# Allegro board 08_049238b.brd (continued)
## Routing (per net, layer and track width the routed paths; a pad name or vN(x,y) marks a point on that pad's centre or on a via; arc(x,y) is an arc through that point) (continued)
D2_10_N: length 102.7
  TOP w0.127: X2.23 43.58,56.71 43.46,56.83 25.06,56.83 13.46,45.23 13.46,36.6 13.14,36.28 12.91,36.28 v2(12.61,35.98)
  L8_SIGNAL w0.127: v2(12.61,35.98) 12.31,36.28 11.87,36.28 11.3,36.85 11.3,44.83 18.03,51.56 18.03,75.84 12.72,81.15 7.78,81.15 7.38,80.76 7.38,80.63 P1.D8
D2_10_P: length 103.1
  TOP w0.127: X2.22 43.58,57.21 43.46,57.09 24.96,57.09 13.21,45.34 13.21,36.71 13.04,36.54 12.91,36.54 v2(12.61,36.84)
  L8_SIGNAL w0.127: P1.C8 7.13,80.63 7.13,80.86 7.67,81.41 12.83,81.41 18.29,75.95 18.29,51.46 11.56,44.73 11.56,36.96 11.98,36.54 12.31,36.54 v2(12.61,36.84)
D2_11_N: length 102.7
  TOP w0.127: X2.21 43.58,57.71 43.46,57.83 24.56,57.83 10.92,44.2 10.92,36.55 10.93,36.55 10.93,36.05 10.65,35.78 10.42,35.78 v2(10.12,35.48)
  L8_SIGNAL w0.127: P1.D7 7.38,78.13 7.38,78.26 7.61,78.49 12.47,78.49 16.76,74.19 16.76,52.2 9.02,44.45 9.02,36.47 9.61,35.88 9.72,35.88 v2(10.12,35.48)
D2_11_P: length 103.1
  TOP w0.127: v2(10.12,36.33) 10.42,36.03 10.55,36.03 10.68,36.16 10.68,36.44 10.67,36.45 10.67,44.3 24.46,58.09 43.46,58.09 43.58,58.21 X2.20
  L8_SIGNAL w0.127: P1.C7 7.13,78.13 7.13,78.36 7.5,78.74 12.57,78.74 17.02,74.3 17.02,52.09 9.27,44.34 9.27,36.58 9.72,36.13 9.93,36.13 v2(10.12,36.33)
D2_12_N: length 102.6
  TOP w0.127: X2.18 44.65,59.77 44.77,59.9 44.77,61.3 43.33,62.74 27.92,62.74 8.89,43.71 8.89,38.25 8.61,37.97 8.3,37.97 v2(8,37.67)
  L8_SIGNAL w0.127: P1.D6 8.01,75.31 7.87,75.44 7.75,75.44 7.65,75.34 7.47,75.34 7.37,75.44 7.37,75.67 7.38,75.69 7.38,75.76 7.51,75.89 12.25,75.89 15.11,73.03 15.11,51.92 6.98,43.79 6.98,38.46 7.47,37.97 7.7,37.97 v2(8,37.67)
D2_12_P: length 103.1
  TOP w0.127: v2(8,38.53) 8.3,38.23 8.51,38.23 8.64,38.35 8.64,43.81 27.81,62.99 43.43,62.99 45.02,61.4 45.02,59.9 45.14,59.77 X2.17
  L8_SIGNAL w0.127: P1.C6 6.98,75.49 6.98,75.72 7.41,76.14 12.38,76.14 15.37,73.15 15.37,51.82 7.24,43.69 7.24,38.56 7.57,38.23 7.7,38.23 v2(8,38.53)
D2_13_N: length 102.6
  TOP w0.127: X2.16 45.65,59.77 45.77,59.9 45.77,61.57 43.71,63.63 27.03,63.63 7.24,43.84 7.24,38.88 6.96,38.61 6.65,38.61 v2(6.35,38.31)
  L8_SIGNAL w0.127: P1.D5 8.01,72.77 7.87,72.9 7.62,72.9 7.49,72.77 7.37,72.77 7.24,72.9 7.24,73.3 7.34,73.41 12.06,73.41 14.1,71.37 14.1,52.56 5.33,43.79 5.33,38.99 5.72,38.61 6.05,38.61 v2(6.35,38.31)
D2_13_P: length 102.9
  TOP w0.127: X2.15 46.14,59.77 46.02,59.9 46.02,61.67 43.81,63.88 26.92,63.88 6.98,43.94 6.98,38.99 6.86,38.86 6.65,38.86 v2(6.35,39.16)
  L8_SIGNAL w0.127: P1.C5 6.6,72.51 6.98,72.9 6.98,73.41 7.24,73.66 12.19,73.66 14.35,71.5 14.35,52.45 5.59,43.69 5.59,39.09 5.82,38.86 6.05,38.86 v2(6.35,39.16)
D2_14_N: length 102.9
  TOP w0.127: v2(4.32,39.08) 4.62,39.38 4.98,39.38 5.2,39.59 5.2,39.87 5.59,40.26 5.59,43.81 26.67,64.9 44.98,64.9 46.36,63.52 46.36,60.4 46.79,59.97 46.79,59.77 46.65,59.63 X2.14
  L8_SIGNAL w0.127: P1.D4 7.85,69.85 7.49,69.85 7.37,69.98 7.37,70.51 7.38,70.53 7.38,70.76 7.51,70.89 12.04,70.89 13.08,69.85 13.08,53.09 3.5,43.5 3.5,39.79 3.78,39.51 3.89,39.51 v2(4.32,39.08)
D2_14_P: length 103.1
  TOP w0.127: X2.13 47.14,59.77 47.04,59.88 47.04,60.07 46.61,60.5 46.61,63.63 45.09,65.15 26.56,65.15 5.33,43.92 5.33,40.36 4.94,39.97 4.94,39.7 4.88,39.63 4.62,39.63 v2(4.32,39.93)
  L8_SIGNAL w0.127: P1.C4 7.13,70.63 7.13,70.86 7.41,71.14 12.17,71.14 13.34,69.98 13.34,52.98 3.75,43.4 3.75,39.9 3.89,39.76 4.16,39.76 v2(4.32,39.93)
D2_15_N: length 102.7
  TOP w0.127: v2(2.12,40.17) 2.42,40.47 3.26,40.47 3.68,40.89 3.68,43.31 26.16,65.79 45.36,65.79 48.64,62.51 48.64,60.56 48.27,60.18 48.27,59.9 48.14,59.77 X2.11
  L8_SIGNAL w0.127: P1.D3 8.01,67.81 7.87,67.94 7.75,67.94 7.62,67.82 7.49,67.82 7.37,67.94 7.37,68.19 7.49,68.32 7.49,68.33 7.62,68.45 9.78,68.45 11.75,66.48 11.75,53.28 3.3,44.83 1.91,44.83 0.76,43.69 0.76,40.77 1.05,40.47 1.82,40.47 v2(2.12,40.17)
D2_15_P: length 103.1
  TOP w0.127: X2.10 48.65,60.2 48.9,60.45 48.9,62.61 45.47,66.04 26.06,66.04 3.43,43.41 3.43,41 3.16,40.73 2.42,40.73 v2(2.12,41.03)
  L8_SIGNAL w0.127: P1.C3 7.11,68.11 7.11,68.45 7.37,68.71 9.91,68.71 12,66.61 12,53.17 3.41,44.58 2.01,44.58 1.02,43.58 1.02,40.87 1.16,40.73 1.82,40.73 v2(2.12,41.03)
D2_N: length 102.6
  TOP w0.127: v2(9.52,131.17) 9.84,131.49 10.41,131.49 10.54,131.37 10.54,130.05 11.43,129.16 14.1,129.16 28.7,114.55 28.7,110.62 33.15,106.17 41.91,106.17 42.42,106.68 44.2,106.68 47.02,109.51 47.02,110.62 47.14,110.74 X1.42
  L3_SIGNAL w0.127: v2(9.52,131.17) 9.21,131.49 8.18,131.49 7.87,131.19 7.87,129.54 16,121.41 16,102.64 15.35,101.98 3.07,101.98 2.88,101.79 2.88,101.67 P2.B6
D2_P: length 102.6
  TOP w0.127: v2(9.52,132.07) 9.84,131.75 10.52,131.75 10.8,131.47 10.8,130.15 11.54,129.41 14.2,129.41 28.96,114.66 28.96,110.72 33.25,106.43 41.8,106.43 42.31,106.93 44.09,106.93 46.77,109.61 46.77,110.62 46.65,110.74 X1.41
  L3_SIGNAL w0.127: P2.A6 2.63,101.67 2.63,101.9 2.96,102.23 15.24,102.23 15.75,102.74 15.75,121.31 7.62,129.43 7.62,131.3 8.07,131.75 9.21,131.75 v2(9.52,132.07)
D3_N: length 102.9
  TOP w0.127: v2(11.81,132.52) 12.13,132.84 12.32,132.84 12.45,132.72 12.45,130.51 12.79,130.18 14.61,130.18 29.46,115.32 29.46,111.51 34.04,106.93 41.4,106.93 41.91,107.44 43.94,107.44 46.02,109.52 46.02,110.62 46.14,110.74 X1.40
  L3_SIGNAL w0.127: v2(11.81,132.52) 11.49,132.84 10.9,132.84 10.67,132.61 10.67,128.38 12.3,126.75 12.32,126.75 17.4,121.67 17.4,101.85 15.09,99.54 11.65,99.54 11.53,99.42 3.01,99.42 2.88,99.29 2.88,99.17 P2.B5
D3_P: length 102.9
  TOP w0.127: X1.39 45.65,110.74 45.77,110.62 45.77,109.63 43.84,107.7 41.8,107.7 41.3,107.19 34.14,107.19 29.72,111.61 29.72,115.42 14.71,130.43 12.89,130.43 12.7,130.62 12.7,132.82 12.42,133.1 12.13,133.1 v2(11.81,133.41)
  L3_SIGNAL w0.127: v2(11.81,133.41) 11.49,133.1 10.8,133.1 10.41,132.72 10.41,128.27 12.19,126.49 12.21,126.49 17.14,121.56 17.14,101.96 14.98,99.8 11.54,99.8 11.42,99.68 2.91,99.68 2.63,99.4 2.63,99.17 P2.A5
D4_N: length 102.7
  TOP w0.127: X1.38 45.14,110.74 45.02,110.62 45.02,109.67 43.56,108.2 41.66,108.2 41.15,107.7 35.43,107.7 30.1,113.03 30.1,115.97 14.5,131.57 13.72,131.57 v2(13.4,131.25)
  L3_SIGNAL w0.127: P2.B4 2.88,96.67 2.88,96.79 3.01,96.92 11.02,96.92 11.04,96.9 17.89,96.9 18.54,97.56 18.54,127.49 18.01,128.02 13.19,128.02 12.81,128.4 12.81,131.44 12.93,131.57 13.08,131.57 v2(13.4,131.25)
D4_P: length 102.7
  TOP w0.127: X1.37 44.65,110.74 44.77,110.62 44.77,109.77 43.46,108.46 41.55,108.46 41.04,107.95 35.54,107.95 30.35,113.14 30.35,116.08 14.61,131.83 13.72,131.83 v2(13.4,132.14)
  L3_SIGNAL w0.127: P2.A4 2.63,96.67 2.63,96.9 2.91,97.18 11.13,97.18 11.15,97.16 17.78,97.16 18.29,97.66 18.29,127.38 17.91,127.76 13.08,127.76 12.55,128.29 12.55,131.55 12.83,131.83 13.08,131.83 v2(13.4,132.14)
D5_N: length 102.7
  TOP w0.127: X1.35 43.58,112.31 43.46,112.43 32.22,112.43 31.12,113.54 31.12,116.35 17.02,130.45 17.02,135.13 16.72,135.43 16.15,135.43 v2(15.83,135.11)
  L3_SIGNAL w0.127: P2.B3 2.88,94.17 2.88,94.29 3.01,94.42 11.61,94.42 11.65,94.46 18.26,94.46 19.56,95.76 19.56,127.87 15.26,132.17 15.26,135.3 15.38,135.43 15.51,135.43 v2(15.83,135.11)
D5_P: length 103.1
  TOP w0.127: X1.34 43.58,112.81 43.46,112.68 32.33,112.68 31.37,113.64 31.37,116.46 17.27,130.56 17.27,135.23 16.82,135.68 16.15,135.68 v2(15.83,136)
  L3_SIGNAL w0.127: P2.A3 2.63,94.17 2.63,94.4 2.91,94.68 11.5,94.68 11.54,94.72 18.16,94.72 19.3,95.86 19.3,127.76 15,132.06 15,135.41 15.28,135.68 15.51,135.68 v2(15.83,136)
D6_N: length 102.6
  TOP w0.127: v2(18.1,135.13) 18.42,135.45 18.55,135.45 18.8,135.2 18.8,133.73 18.54,133.48 18.54,130.3 32.13,116.71 32.13,114.17 32.87,113.43 43.46,113.43 43.58,113.31 X1.33
  L3_SIGNAL w0.127: P2.B2 2.88,91.67 2.88,91.79 3.29,92.2 17.53,92.2 20.45,95.12 20.45,128.52 17.91,131.06 17.53,131.06 17.14,131.44 17.14,134.87 17.53,135.26 17.53,135.32 17.66,135.45 17.78,135.45 v2(18.1,135.13)
D6_P: length 103.1
  TOP w0.127: X1.32 43.58,113.81 43.46,113.68 32.98,113.68 32.39,114.28 32.39,116.82 18.8,130.41 18.8,133.37 19.05,133.63 19.05,135.31 18.65,135.7 18.42,135.7 v2(18.1,136.02)
  L3_SIGNAL w0.127: v2(18.1,136.02) 17.78,135.7 17.55,135.7 17.28,135.43 17.28,135.36 16.89,134.98 16.89,131.34 17.42,130.81 17.8,130.81 20.19,128.42 20.19,95.23 17.42,92.46 3.19,92.46 2.63,91.9 2.63,91.67 P2.A2
D7_N: length 102.6
  TOP w0.127: X1.31 43.58,114.31 43.46,114.43 34.16,114.43 33.27,115.32 33.27,117.09 22.61,127.76 22.61,131.72 20.6,133.73 20.32,133.73 v2(20,133.41)
  L3_SIGNAL w0.127: P2.B1 2.88,89.17 2.88,89.29 3.25,89.66 13.46,89.66 14.22,88.9 21.08,88.9 21.72,89.53 21.72,131.68 21.19,132.21 20.17,132.21 19.3,133.07 19.3,133.48 19.56,133.73 19.68,133.73 v2(20,133.41)
D7_P: length 103.1
  TOP w0.127: X1.30 43.58,114.81 43.46,114.68 34.27,114.68 33.53,115.42 33.53,117.2 22.86,127.87 22.86,131.83 20.7,133.99 20.32,133.99 v2(20,134.3)
  L3_SIGNAL w0.127: v2(20,134.3) 19.68,133.99 19.45,133.99 19.05,133.58 19.05,132.97 20.07,131.95 21.08,131.95 21.46,131.57 21.46,89.64 20.98,89.15 14.33,89.15 13.57,89.92 3.15,89.92 2.63,89.4 2.63,89.17 P2.A1
D8_N: length 102.7
  TOP w0.127: v2(22.73,134.3) 23.05,134.62 23.5,134.62 23.62,134.49 23.62,128.5 35.69,116.43 43.46,116.43 43.58,116.31 X1.27
  L3_SIGNAL w0.127: P1.B10 2.88,85.63 2.88,85.76 3.1,85.98 21.21,85.98 22.73,87.5 22.73,132.46 21.72,133.48 21.72,134.39 21.95,134.62 22.39,134.62 22.52,134.49 22.52,134.41 22.63,134.3 v2(22.73,134.3)
D8_P: length 103.1
  TOP w0.127: X1.26 43.58,116.81 43.46,116.68 35.8,116.68 23.88,128.61 23.88,134.6 23.6,134.87 23.05,134.87 v2(22.73,135.19)
  L3_SIGNAL w0.127: v2(22.73,135.19) 22.41,134.87 21.84,134.87 21.46,134.49 21.46,133.37 22.48,132.36 22.48,87.61 21.1,86.23 3,86.23 2.63,85.86 2.63,85.63 P1.A10
D9_N: length 102.9
  TOP w0.127: X1.25 43.58,117.31 43.46,117.43 36.64,117.43 26.54,127.53 26.54,129.56 24.91,131.2 24.91,131.59 25.08,131.76 25.08,133.6 24.96,133.73 24.83,133.73 v2(24.51,133.41)
  L3_SIGNAL w0.127: P1.B9 3.09,82.51 2.79,82.8 2.79,82.94 2.88,83.03 2.88,83.26 3.06,83.44 17.53,83.44 17.91,83.06 22.99,83.06 24.13,84.2 24.13,88.37 23.88,88.62 23.88,133.54 24.07,133.73 24.19,133.73 v2(24.51,133.41)
D9_P: length 103
  TOP w0.127: X1.24 43.58,117.81 43.46,117.68 36.75,117.68 26.8,127.64 26.8,129.67 25.16,131.3 25.16,131.48 25.34,131.66 25.34,133.71 25.06,133.99 24.83,133.99 v2(24.51,134.3)
  L3_SIGNAL w0.127: P1.A9 2.63,83.13 2.63,83.36 2.96,83.69 17.63,83.69 18.01,83.31 22.88,83.31 23.88,84.31 23.88,88.27 23.62,88.52 23.62,133.65 23.96,133.99 24.19,133.99 v2(24.51,134.3)
D10_N: length 102.7
  TOP w0.127: v2(27.05,133.41) 27.37,133.73 27.56,133.73 27.69,133.6 27.69,127.89 37.15,118.43 43.46,118.43 43.58,118.31 X1.23
  L3_SIGNAL w0.127: v2(27.05,133.41) 26.73,133.73 26.54,133.73 25.78,132.97 25.78,84.22 22.58,81.03 3.15,81.03 2.88,80.76 2.88,80.63 P1.B8
D10_P: length 103.1
  TOP w0.127: v2(27.05,134.3) 27.37,133.99 27.66,133.99 27.94,133.71 27.94,127.99 37.25,118.68 43.46,118.68 43.58,118.81 X1.22
  L3_SIGNAL w0.127: P1.A8 2.63,80.63 2.63,80.86 3.04,81.28 22.48,81.28 25.53,84.33 25.53,133.07 26.44,133.99 26.73,133.99 v2(27.05,134.3)
D11_N: length 102.7
  TOP w0.127: X1.21 43.58,119.31 43.46,119.43 37.67,119.43 29.08,128.02 29.08,132.56 29.15,132.63 29.15,133.22 29.02,133.35 28.89,133.35 v2(28.57,133.03)
  L3_SIGNAL w0.127: P1.B7 2.88,78.13 2.88,78.26 3.11,78.49 21.84,78.49 26.8,83.44 26.8,132.02 28.13,133.35 28.26,133.35 v2(28.57,133.03)
D11_P: length 103.1
  TOP w0.127: X1.20 43.58,119.81 43.46,119.68 37.77,119.68 29.34,128.12 29.34,132.46 29.4,132.52 29.4,133.33 29.13,133.6 28.89,133.6 v2(28.57,133.92)
  L3_SIGNAL w0.127: P1.A7 2.63,78.13 2.63,78.36 3,78.74 21.74,78.74 26.54,83.54 26.54,132.12 28.02,133.6 28.26,133.6 v2(28.57,133.92)
D12_N: length 102.7
  TOP w0.127: X1.18 44.65,121.37 44.77,121.49 44.77,123.89 44.45,124.21 35.94,124.21 33.91,126.24 33.91,127.89 33.4,128.4 31.62,128.4 31.24,128.78 31.24,131.06 31.12,131.19 30.93,131.19 v2(30.61,130.87)
  L3_SIGNAL w0.127: P1.B6 3.43,75.09 3.43,75.56 3.3,75.69 3.17,75.69 3.07,75.59 2.89,75.59 2.79,75.69 2.79,76.06 2.92,76.18 21.32,76.18 27.56,82.42 27.81,82.42 27.94,82.55 27.94,129.54 29.59,131.19 30.29,131.19 v2(30.61,130.87)
D12_P: length 103.1
  TOP w0.127: X1.17 45.14,121.37 45.02,121.49 45.02,124.14 44.7,124.46 36.05,124.46 34.16,126.34 34.16,127.99 33.51,128.65 31.88,128.65 31.5,129.03 31.5,131.17 31.22,131.44 30.93,131.44 v2(30.61,131.76)
  L3_SIGNAL w0.127: P1.A6 2.54,75.54 2.54,76.16 2.82,76.44 21.21,76.44 27.45,82.68 27.69,82.68 27.69,129.67 29.46,131.44 30.29,131.44 v2(30.61,131.76)
D13_N: length 102.6
  TOP w0.127: v2(32.26,129.48) 32.58,129.79 34.29,129.79 34.67,129.41 34.67,127 36.58,125.09 44.7,125.09 45.77,124.03 45.77,121.49 45.65,121.37 X1.16
  L3_SIGNAL w0.127: v2(32.26,129.48) 31.94,129.79 30.23,129.79 29.08,128.65 29.08,81.43 21.19,73.53 3.15,73.53 2.92,73.3 2.92,72.9 2.82,72.8 2.82,72.62 2.92,72.52 3.5,72.52 P1.B5
D13_P: length 103.1
  TOP w0.127: v2(32.26,130.37) 32.58,130.05 34.4,130.05 34.92,129.52 34.92,127.11 36.68,125.35 44.83,125.35 46.02,124.16 46.02,121.49 46.14,121.37 X1.15
  L3_SIGNAL w0.127: v2(32.26,130.37) 31.94,130.05 30.12,130.05 28.83,128.76 28.83,81.53 21.08,73.79 3.05,73.79 2.67,73.41 2.67,73.17 P1.A5
D14_N: length 102.8
  TOP w0.127: v2(35.94,128.59) 36.26,128.91 36.83,128.91 37.21,128.53 37.21,126.49 37.59,126.11 45.59,126.11 46.36,125.35 46.36,122.03 46.74,121.65 46.74,121.41 46.65,121.32 X1.14
  L3_SIGNAL w0.127: P1.B4 3.51,70.41 3.42,70.5 3.19,70.5 3.05,70.36 2.87,70.36 2.83,70.4 2.83,70.57 2.79,70.61 2.79,70.76 2.99,70.96 20.8,70.96 30.73,80.9 30.73,99.57 31.37,100.2 31.37,125.88 34.4,128.91 35.62,128.91 v2(35.94,128.59)
D14_P: length 103
  TOP w0.127: v2(35.94,129.48) 36.26,129.16 36.94,129.16 37.47,128.63 37.47,126.6 37.7,126.37 45.72,126.37 46.61,125.48 46.61,122.14 47.14,121.6 X1.13
  L3_SIGNAL w0.127: P1.A4 2.41,70.42 2.41,70.74 2.89,71.22 20.67,71.22 30.48,81.03 30.48,99.67 31.12,100.31 31.12,125.98 34.29,129.16 35.62,129.16 v2(35.94,129.48)
D15_N: length 102.9
  TOP w0.127: v2(39.24,127.06) 39.56,127.38 46.63,127.38 48.64,125.37 48.64,122.1 48.39,121.85 48.39,121.61 48.14,121.37 X1.11
  L3_SIGNAL w0.127: P1.B3 3.51,67.99 3.42,68.08 3.19,68.08 3.05,67.94 2.92,67.94 2.79,68.07 2.79,68.45 2.92,68.58 20.45,68.58 32.64,80.77 32.64,123.72 36.3,127.38 38.92,127.38 v2(39.24,127.06)
D15_P: length 103.1
  TOP w0.127: X1.10 48.65,121.74 48.9,121.99 48.9,125.48 46.74,127.64 39.56,127.64 v2(39.24,127.95)
  L3_SIGNAL w0.127: P1.A3 2.54,68.04 2.54,68.58 2.79,68.83 20.34,68.83 32.39,80.88 32.39,123.83 36.2,127.64 38.92,127.64 v2(39.24,127.95)
DACCK2_N: length 43.7
  L8_SIGNAL w0.127: v2(56.77,84.45) 57.28,83.95 58.93,83.95 64.01,78.87 64.01,55.44 61.85,53.28 61.43,53.28 v2(61.13,52.98)
  BOTTOM w0.127: U1.28 53.97,84.99 54.09,84.87 54.72,84.87 55.51,84.07 56.39,84.07 v2(56.77,84.45) R28.1 ; C119.1 60.01,52.83 60.14,52.96 60.14,53.15 60.26,53.28 60.45,53.28 60.83,53.28 v2(61.13,52.98)
DACCK2_P: length 43.4
  L8_SIGNAL w0.127: v2(56.77,83.31) 56.64,83.44 56.64,83.69 56.77,83.82 56.9,83.82 57.02,83.69 58.8,83.69 63.75,78.74 63.75,55.54 61.74,53.53 61.43,53.53 v2(61.13,53.83)
  BOTTOM w0.127: R27.1 v2(56.77,83.31) 56.77,83.44 56.39,83.82 55.4,83.82 54.61,84.61 54.09,84.61 53.97,84.49 U1.29 ; C109.1 60.01,53.98 60.14,53.85 60.14,53.66 60.26,53.53 60.35,53.53 60.83,53.53 v2(61.13,53.83)
DACCK_N: length 43.2
  L8_SIGNAL w0.127: v2(61.02,114.59) 61.02,114.87 61.06,114.91 61.87,114.91 63.75,113.03 63.75,89.28 61.47,87 56.77,87 56.64,87.12 v2(56.64,87.63)
  BOTTOM w0.127: C133.1 59.75,114.4 59.88,114.53 59.88,114.78 60.01,114.91 60.71,114.91 v2(61.02,114.59) ; R42.1 v2(56.64,87.63) 56.26,87.25 55.65,87.25 54.77,86.37 54.09,86.37 53.97,86.49 U1.25
DACCK_P: length 43.5
  L8_SIGNAL w0.127: v2(56.64,86.49) 56.9,86.74 61.57,86.74 64.01,89.18 64.01,113.14 61.98,115.16 61.34,115.16 v2(61.02,115.48)
  BOTTOM w0.127: v2(61.02,115.48) 60.71,115.16 60.01,115.16 59.88,115.29 59.88,115.54 59.75,115.67 C93.1 ; R7.1 v2(56.64,86.49) 56.13,87 55.75,87 54.87,86.11 54.09,86.11 53.97,85.99 U1.26
DCI1_N: length 102.6
  TOP w0.127: X1.29 43.58,115.31 43.46,115.43 35.24,115.43 35,115.19 v2(34.92,115.19)
  L3_SIGNAL w0.127: P1.B2 2.88,65.63 2.88,65.76 3.16,66.04 11.96,66.04 21.87,56.13 28.83,56.13 33.53,60.83 33.53,114.48 34.48,115.43 34.61,115.43 34.85,115.19 v2(34.92,115.19)
DCI1_P: length 103.1
  TOP w0.127: X1.28 43.58,115.81 43.46,115.68 35.24,115.68 v2(34.92,116)
  L3_SIGNAL w0.127: P1.A2 2.63,65.63 2.63,65.86 3.06,66.29 12.06,66.29 21.97,56.39 28.72,56.39 33.27,60.94 33.27,114.58 34.37,115.68 34.61,115.68 v2(34.92,116)
DCI2_N: length 102.7
  TOP w0.127: v2(33.66,53.59) 33.78,53.72 33.8,53.72 33.91,53.83 43.46,53.83 43.58,53.71 X2.29
  L8_SIGNAL w0.127: P2.D9 7.38,109.17 7.38,109.29 7.56,109.47 10.16,109.47 10.8,110.11 10.8,115.95 11.3,116.46 14.63,116.46 14.99,116.1 14.99,109.73 15.49,109.22 16.28,109.22 23.9,101.6 30.76,101.6 32.39,99.97 32.39,85.45 30.48,83.54 30.48,55.65 32.28,53.85 33.3,53.85 33.42,53.72 33.53,53.72 v2(33.66,53.59)
DCI2_P: length 103
  TOP w0.127: X2.28 43.58,54.21 43.46,54.09 33.98,54.09 33.67,54.4 v2(33.6,54.4)
  L8_SIGNAL w0.127: v2(33.6,54.4) 33.3,54.1 32.39,54.1 30.73,55.75 30.73,83.44 32.64,85.34 32.64,100.08 30.86,101.85 24,101.85 16.38,109.47 15.6,109.47 15.24,109.83 15.24,116.2 14.73,116.71 11.2,116.71 10.54,116.06 10.54,110.34 9.93,109.73 7.46,109.73 7.13,109.4 7.13,109.17 P2.C9
DCO_N: length 38.8
  L3_SIGNAL w0.127: v2(34.8,80.96) 35.12,80.64 42.42,80.64 43.05,80.01 43.05,79.38 42.67,78.99 42.1,78.99 v2(41.78,78.68)
  BOTTOM w0.127: v2(34.8,80.96) 34.48,80.64 28.7,80.64 22.35,87 18.03,87 17.4,87.63 16.87,87.63 U3.9 ; U1.45 46.65,81.66 46.52,81.54 46.52,80.94 44.58,78.99 42.1,78.99 v2(41.78,78.68)
DCO_P: length 37.6
  L3_SIGNAL w0.127: v2(41.78,79.57) 42.1,79.25 42.57,79.25 42.8,79.48 42.8,79.9 42.31,80.39 35.12,80.39 v2(34.8,80.07)
  BOTTOM w0.127: U3.12 16.87,86.11 17.4,86.11 18.03,86.74 22.25,86.74 28.6,80.39 34.48,80.39 v2(34.8,80.07) ; v2(41.78,79.57) 42.1,79.25 44.47,79.25 46.27,81.04 46.27,81.54 46.14,81.66 U1.46
FILT_1_N: length 4.6
  TOP w0.254: JP5.3 C23.2
  TOP w0.61: L11.1 C23.2
FILT_1_P: length 4.6
  TOP w0.254: JP4.3 C23.1
  TOP w0.61: L10.1 C23.1
FILT_2_N: length 4.3
  TOP w0.254: 65.28,83.19 C74.2
  TOP w0.61: L8.1 C74.2
FILT_2_P: length 4.3
  TOP w0.254: JP6.3 C97.2
  TOP w0.61: C97.2 L9.1
FRAME1_N: length 80.6
  TOP w0.127: v2(56.64,128.44) 56.57,128.37 56.57,128.15 56.44,128.02 55.98,128.02 52.05,131.95 50.42,131.95 48.77,130.3 48.77,126.26 49.27,125.76 49.27,121.49 49.14,121.37 X1.9
  L8_SIGNAL w0.127: v2(54.06,77.68) 54.36,77.98 55.48,77.98 56.01,78.51 56.01,88.54 58.29,90.83 58.29,107.08 58.55,107.34 58.55,111.74 57.91,112.37 57.91,127.87 57.64,128.14 56.94,128.14 v2(56.64,128.44)
  BOTTOM w0.127: v2(54.06,77.68) 53.76,77.98 52.73,77.98 52.27,78.44 52.27,81.54 52.14,81.66 U1.34
FRAME1_P: length 80.3
  TOP w0.127: X1.8 49.65,121.37 49.52,121.49 49.52,125.86 49.02,126.37 49.02,130.18 50.55,131.7 51.94,131.7 55.89,127.75 55.89,127.12 56.01,127 56.13,127 56.39,126.75 56.52,126.75 56.77,127 56.77,127.46 v2(56.64,127.59)
  L8_SIGNAL w0.127: v2(56.64,127.59) 56.94,127.89 57.53,127.89 57.66,127.76 57.66,112.27 58.29,111.63 58.29,107.44 58.04,107.19 58.04,90.93 55.75,88.65 55.75,78.61 55.37,78.23 54.36,78.23 v2(54.06,78.53)
  BOTTOM w0.127: U1.33 52.65,81.66 52.52,81.54 52.52,78.54 52.83,78.23 53.76,78.23 v2(54.06,78.53)
FRAME2_N: length 80.2
  TOP w0.127: X2.9 49.14,59.77 49.27,59.9 49.27,60.42 49.4,60.56 49.4,62.89 47.24,65.05 47.24,68.67 46.96,68.96 46.83,68.96 v2(46.53,68.66)
  BOTTOM w0.127: v2(46.53,68.66) 46.23,68.96 45.44,68.96 43.41,66.93 36.81,66.93 34.16,64.28 34.16,63.48 36.58,61.07 36.58,57.68 35.92,57.02 33.15,57.02 28.57,61.59 28.57,66.91 29.99,68.33 40.53,68.33 49.55,77.34 50.19,77.34 51.27,78.42 51.27,81.54 51.14,81.66 U1.36
FRAME2_P: length 80.2
  TOP w0.127: v2(46.53,69.52) 46.83,69.22 47.06,69.22 47.5,68.78 47.5,65.15 49.66,62.99 49.66,60.45 49.52,60.32 49.52,59.9 49.65,59.77 X2.8
  BOTTOM w0.127: U1.35 51.65,81.66 51.52,81.54 51.52,78.32 50.29,77.09 49.66,77.09 40.64,68.07 30.1,68.07 28.83,66.8 28.83,61.7 33.25,57.28 35.81,57.28 36.32,57.78 36.32,60.96 33.91,63.37 33.91,64.39 36.7,67.18 43.31,67.18 45.34,69.22 46.23,69.22 v2(46.53,69.52)
IBB_N: length 24.4
  TOP w0.127: R200.2 89.52,90.81 ; 89.52,90.81 89.9,90.42 89.9,88.85 U4.22 ; 89.52,90.81 89.92,91.2 89.92,95.02 89.43,95.5 84.56,95.5 79.86,90.81 76.45,90.81 C44.2
  TOP w0.61: L6.2 C44.2
IBB_P: length 25
  TOP w0.127: U4.21 90.19,88.85 90.19,90.42 90.57,90.81 ; 90.57,90.81 90.17,91.2 90.17,95.12 89.53,95.76 84.45,95.76 79.76,91.06 76.33,91.06 75.82,91.57 ; 90.57,90.81 R200.1
  TOP w0.61: L5.2 75.82,91.57 C49.2
INTB: length 135.5
  TOP w0.203: v1(60.96,9.65) 47.24,9.65 43.9,13 XU2.21 ; X1.51 51.65,102.45 51.18,101.98 v1(51.18,101.85) CR5.C
  L3_SIGNAL w0.203: v1(51.18,101.85) 53.09,103.76 59.94,103.76 61.21,102.49 61.21,89.92 62.23,88.9 62.23,78.99 61.72,78.49 61.72,35.94 60.83,35.05 60.83,32.13 61.59,31.37 61.59,10.29 v1(60.96,9.65)
INTB2: length 136
  TOP w0.203: X1.50 51.14,106.59 v1(49.94,105.38) CR6.C ; XU2.22 44.55,13.11 47.12,10.54 v1(58.93,10.54)
  L3_SIGNAL w0.203: v1(58.93,10.54) 58.93,9.52 59.82,8.64 61.34,8.64 62.1,9.4 62.1,31.75 61.34,32.51 61.34,34.67 62.1,35.43 62.1,78.23 62.61,78.74 62.61,89.15 61.85,89.92 61.85,102.74 59.94,104.65 50.8,104.65 50.06,105.38 v1(49.94,105.38)
INTB2_2: length 43
  TOP w0.203: X2.50 51.14,45.05 v1(49.91,43.81) 49.91,42.62 DS4.C ; v1(48.01,13.34) 47.5,13.34 45.91,14.93 XU2.24
  BOTTOM w0.203: v1(49.91,43.81) 48.84,43.81 48.64,43.61 48.64,13.84 48.13,13.34 v1(48.01,13.34)
INTB_2: length 43.5
  TOP w0.203: v1(49.28,12.19) 47.75,12.19 45.67,14.28 XU2.23 ; X2.51 51.65,42.12 49.94,40.41 DS3.C v1(49.94,39.27)
  BOTTOM w0.203: v1(49.94,39.27) 49.94,20.85 49.02,19.94 49.02,12.45 v1(49.28,12.19)
INTERNAL_MOSI: length 40.3
  TOP w0.203: v1(34.67,24.38) 33.53,24.38 R26.1 33.16,24.75 XU3.12 33.16,29.61 35.43,31.88 55.63,31.88 57.8,29.7 XU1.12 ; XU2.1 34.85,20.78 v1(34.67,20.95)
  BOTTOM w0.203: v1(34.67,20.95) v1(34.67,24.38)
INTERNAL_SCK: length 57.5
  TOP w0.203: XU2.10 36.9,14.93 35.56,13.59 29.72,13.59 v1(29.08,14.22) ; XU1.13 58.45,29.94 55.83,32.56 36.32,32.56 v1(36.27,32.61) ; XU3.13 v1(33.81,28.67)
  BOTTOM w0.203: v1(36.27,32.61) 36.27,32.59 33.81,30.13 v1(33.81,28.67) 32.1,28.67 29.08,25.65 v1(29.08,14.22)
MISO2: length 81.4
  TOP w0.203: XU3.4 32.51,36.83 v1(32.39,36.96)
  L3_SIGNAL w0.203: v1(32.39,36.96) 34.92,36.96 35.31,37.34 35.31,63.02 37.82,65.53 46.61,65.53 60.58,79.5 60.58,88.01 59.31,89.28 54.86,89.28 v2(54.48,88.9)
  BOTTOM w0.203: v2(54.48,88.9) 54.07,88.49 U1.21
MOSI1: length 119.8
  TOP w0.203: v1(57.78,36.32) 57.78,34.43 XU1.3 57.8,33.13 58.8,32.13 63.88,32.13 v1(64.01,32) ; X1.52 52.14,111.81 51.69,112.27 v2(51.69,112.4) ; X2.52 52.14,50.09 v2(51.63,50.61)
  L3_SIGNAL w0.203: v2(51.63,50.61) 51.63,44.64 56.77,39.5 56.77,37.34 v1(57.78,36.32) ; v1(52.32,107.95) 60.07,107.95 64.01,104.01 64.01,77.85 63.37,77.22 63.37,35.05 64.01,34.42 v1(64.01,32)
  L8_SIGNAL w0.203: v2(51.69,112.4) 51.69,108.59 v1(52.32,107.95)
MOSI2: length 78.1
  TOP w0.203: XU3.3 33.16,36.84 v1(34.54,38.23)
  L3_SIGNAL w0.203: v2(54.99,88.27) 55.5,88.77 58.93,88.77 59.94,87.76 59.94,79.63 46.23,65.91 37.66,65.91 34.92,63.18 34.92,38.61 v1(34.54,38.23)
  BOTTOM w0.203: U1.22 54.23,87.99 54.38,88.14 54.86,88.14 v2(54.99,88.27)
Q1_N: length 36.7
  BOTTOM w0.127: P1.B1 3.51,62.43 2.92,61.85 2.92,61.19 3.28,60.83 9.84,60.83 12.22,63.21 12.22,85.57 13.13,86.48 13.63,86.48 13.76,86.62 U3.2
Q1_P: length 37.1
  BOTTOM w0.127: U3.1 13.76,86.12 13.65,86.23 13.24,86.23 12.47,85.46 12.47,63.32 12.47,63.32 12.47,63.11 9.94,60.58 3.17,60.58 2.67,61.09 2.67,61.85 P1.A1
Q2_N: length 30.1
  BOTTOM w0.127: U3.4 13.76,87.62 13.63,87.48 13.23,87.48 12.45,88.27 12.45,106.81 12.47,106.83 12.47,106.85 12.97,107.35 12.97,108.82 12.06,109.73 7.62,109.73 7.49,109.85 7.49,110.53 P2.D10
Q2_P: length 30.7
  BOTTOM w0.127: P2.C10 7.11,110.44 7.11,109.85 7.49,109.47 11.96,109.47 12.72,108.72 12.72,107.46 12.29,107.03 12.22,106.96 12.22,106.94 12.19,106.91 12.19,88.16 13.12,87.23 13.65,87.23 13.76,87.12 U3.3
QBB_N: length 24
  TOP w0.127: C99.2 76.45,82.68 80.01,82.68 84.45,78.23 89.3,78.23 89.92,78.85 89.92,81.91 R202.1 89.52,82.42 89.9,82.8 89.9,84.63 U4.9
  TOP w0.61: L7.2 C99.2
QBB_P: length 24.4
  TOP w0.127: C100.2 76.45,82.42 79.9,82.42 84.35,77.98 89.41,77.98 90.17,78.74 90.17,81.91 R202.2 90.57,82.42 90.19,82.8 90.19,84.63 U4.10
  TOP w0.61: L13.2 C100.2
REFCK2_N: length 61.7
  L8_SIGNAL w0.127: v2(52.2,66.88) 51.9,67.18 43.41,67.18 37.57,61.34 35.45,61.34 34.29,62.51 34.29,65.26 35.71,66.67 37.87,66.67 40.79,69.6 42.95,69.6 45.34,71.99 45.34,84.22 44.98,84.58 43.31,84.58 42.42,83.69 42.04,83.69 41.78,83.44 v2(41.78,83.31)
  BOTTOM w0.127: C108.1 52.13,65.47 52.26,65.6 52.26,66.28 52.75,66.77 52.75,67.06 52.62,67.18 52.5,67.18 v2(52.2,66.88) ; U1.52 43.82,84.49 43.7,84.61 43.34,84.61 42.42,83.69 42.04,83.69 41.91,83.57 41.91,83.44 v2(41.78,83.31) 41.15,83.31 R32.1
REFCK2_P: length 61.9
  L8_SIGNAL w0.127: v2(52.2,67.74) 51.9,67.44 43.31,67.44 37.47,61.59 35.56,61.59 34.54,62.61 34.54,65.15 35.81,66.42 37.97,66.42 40.89,69.34 43.05,69.34 45.59,71.88 45.59,84.33 45.09,84.84 43.2,84.84 42.43,84.06 42.05,84.06 v2(41.78,84.33)
  BOTTOM w0.127: U1.53 43.82,84.99 43.7,84.87 43.23,84.87 42.31,83.95 42.04,83.95 41.91,84.07 41.91,84.2 v2(41.78,84.33) R33.1 ; C104.1 52.64,65.47 52.51,65.6 52.51,66.18 53.01,66.67 53.01,67.16 52.73,67.44 52.5,67.44 v2(52.2,67.74)
REFCK_N: length 61.6
  L8_SIGNAL w0.127: v2(41.78,86.49) 42.29,87 42.67,87 43.43,87.76 43.94,87.76 44.58,88.39 44.58,91.69 45.21,92.33 45.21,104.75 40.89,109.07 40.89,123.83 45.97,128.91 50.23,128.91 50.48,128.65 v2(50.55,128.65)
  BOTTOM w0.127: C107.1 52.01,126.68 52.13,126.81 52.13,128.61 51.84,128.91 50.86,128.91 50.61,128.65 v2(50.55,128.65) ; R23.1 v2(41.78,86.49) 42.04,86.74 42.04,86.87 42.16,87 42.42,87 43.3,86.11 43.7,86.11 43.82,85.99 U1.55
REFCK_P: length 61.9
  L8_SIGNAL w0.127: v2(41.78,87.63) 42.16,87.25 42.57,87.25 43.33,88.01 43.84,88.01 44.32,88.5 44.32,91.8 44.96,92.43 44.96,104.65 40.64,108.97 40.64,123.93 45.87,129.16 50.23,129.16 v2(50.55,129.48)
  BOTTOM w0.127: C103.1 52.51,126.68 52.39,126.81 52.39,128.71 51.94,129.16 50.86,129.16 v2(50.55,129.48) ; U1.56 43.82,86.49 43.7,86.37 43.4,86.37 42.52,87.25 42.16,87.25 v2(41.78,87.63) R44.1
SCK1: length 119.1
  TOP w0.203: v1(58.42,37.21) 58.45,37.18 XU1.2 58.45,33.24 58.8,32.89 v1(62.48,32.89) ; v2(52.56,112.4) 52.56,111.95 52.65,111.87 X1.53 ; X2.53 v2(52.65,50.48)
  L3_SIGNAL w0.203: v2(52.56,112.4) 52.28,112.11 52.28,112.09 51.44,111.25 51.44,106.4 51.79,106.05 58.04,106.05 58.42,105.66 60.07,105.66 62.87,102.87 62.87,89.92 63.25,89.53 63.25,78.61 62.48,77.85 v1(62.48,32.89) ; v1(58.42,37.21) 58.42,49.91 57.4,50.93 53.09,50.93 52.65,50.49 v2(52.65,50.48)
SCK2: length 84.2
  TOP w0.203: XU3.2 v1(33.81,35.4)
  L3_SIGNAL w0.203: v1(33.81,35.4) 35.4,35.4 36.32,36.32 36.32,62.74 38.23,64.64 47.12,64.64 61.59,79.12 61.59,88.77 58.17,92.2 53.59,92.2 v1(53.47,92.08)
  BOTTOM w0.203: v1(53.47,92.08) 53.21,91.82 53.21,91.81 U1.16
SSEL1: length 97.3
  TOP w0.203: v1(53.72,107.19) 53.72,110.49 53.14,111.07 X1.54 ; XU1.5 56.52,34.4 56.52,32.89 57.91,31.5 62.74,31.5 v1(62.87,31.37)
  L3_SIGNAL w0.203: v1(53.72,107.19) 53.85,107.31 59.82,107.31 63.63,103.5 63.63,78.11 62.87,77.34 62.87,34.8 63.5,34.16 63.5,32.77 62.87,32.13 v1(62.87,31.37)
SSEL2: length 83.7
  TOP w0.203: XU3.5 31.86,35.57 31.5,35.94 v1(31.5,36.2)
  L3_SIGNAL w0.203: v1(55.3,90.49) 58.99,90.49 61.09,88.39 61.09,79.38 46.86,65.15 37.97,65.15 35.69,62.87 35.69,36.7 35.18,36.2 v1(31.5,36.2)
  BOTTOM w0.203: U1.17 v1(55.3,90.49)
SSEL3: length 17.3
  TOP w0.203: X2.54 53.72,49.05 53.72,46.48 53.21,45.97 53.21,43.69 56.77,40.13 56.77,36.07 57.15,35.69 XU1.4
UNNAMED_1_ADL5375_I71_LOIN: length 3.9
  TOP w0.203: C22.2 85.09,86.49 U4.4
UNNAMED_1_ADL5375_I71_LOIP: length 3.8
  TOP w0.203: U4.3 85.09,86.99 84.58,87.5 C8.2
UNNAMED_1_ADL5375_I71_RFOUT: length 4.2
  TOP w0.203: U4.16 95.61,86.99 95.62,87 C32.1
UNNAMED_1_CAP_I74_N1: length 35.5
  TOP w0.203: C8.1 v1(83.19,88.65)
  BOTTOM w0.203: v1(83.19,88.65) 83.19,77.47 arc(84.19,75.05) 86.61,74.04 J15.1
UNNAMED_1_CAP_I75_N2: length 6.9
  TOP w0.203: C32.2 J6.1
UNNAMED_1_CAP_I93_N1: length 2.5
  TOP w0.61: L9.2 C64.1 L13.1
UNNAMED_1_CAP_I96_N1: length 2.5
  TOP w0.61: L7.1 C75.2 L8.2
UNNAMED_1_CAP_I110_N1: length 2.5
  TOP w0.61: L11.2 C48.2 L6.1
UNNAMED_1_CAP_I116_N1: length 2.5
  TOP w0.61: L5.1 C48.1 L10.2
UNNAMED_2_ADG3304_I104_EN: length 2.3
  TOP w0.203: XR1.2 53.05,28.58 XU1.8
UNNAMED_2_ADG3304_I104_Y3: length 26.1
  TOP w0.203: XU2.40 40.65,22.34 39.62,23.37 39.62,26.03 44.7,31.12 55.5,31.12 57.15,29.46 XU1.11
UNNAMED_2_ADG3304_I104_Y4: length 21.4
  TOP w0.203: XU2.38 41.95,22.18 41.53,22.61 41.53,26.03 41.91,26.42 47.62,26.42 48.39,27.18 56.25,27.18 56.5,27.43 XU1.10
UNNAMED_2_ADG3304_I105_EN: length 2.3
  TOP w0.203: XR5.2 30.52,27.22 XU3.8
UNNAMED_2_ADG3304_I105_Y3: length 22.1
  TOP w0.203: XU2.9 36.53,15.58 35.43,14.48 30.99,14.48 v1(30.23,15.24) ; XU3.11 32.51,24.89 R26.2 v1(30.48,24.51)
  BOTTOM w0.203: v1(30.48,24.51) 29.72,23.75 29.72,15.75 v1(30.23,15.24)
UNNAMED_2_ADG3304_I105_Y4: length 14.4
  TOP w0.203: XU2.39 41.3,22.2 41.02,22.48 41.02,24.64 v1(40.51,25.15) ; v1(31.88,25.53) 31.88,27.16 XU3.10
  BOTTOM w0.203: v1(31.88,25.53) 32.13,25.27 40.39,25.27 v1(40.51,25.15)
UNNAMED_2_CAP_I4_N1: length 17.1
  TOP w0.305: XU2.32 47.68,20.13 49.02,21.46 51.14,21.46 XR3.1 51.4,21.21 56.13,21.21 56.95,20.39 XY1.1 56.95,15.98 XC1.1
UNNAMED_2_CAP_I5_N1: length 12.9
  TOP w0.305: XU2.33 46.18,20.78 48.51,23.11 51.17,23.11 XR3.2 54.55,23.13 XY1.3 54.55,25.77 XC2.1
UNNAMED_2_CAP_I110_N1: length 2
  TOP w0.203: XU2.37 42.6,23.48 XC3.1
UNNAMED_2_CN6P_I38_N1: length 11.1
  TOP w0.203: XP1.1 47.98,7.65 46.48,9.14 42.44,9.14 41.3,10.29 XU2.17
UNNAMED_2_CN6P_I38_N3: length 6.8
  TOP w0.203: XU2.16 40.65,10.15 42.95,7.85 XP1.3
UNNAMED_2_CN6P_I38_N4: length 6.1
  TOP w0.203: XU2.15 40,9.78 40.41,9.37 XP1.4
UNNAMED_2_CN6P_I38_N5: length 11.3
  TOP w0.203: XU2.18 v1(41.95,10.88) ; XP1.5 37.91,7.61 XR2.2
  BOTTOM w0.203: XP1.5 41.11,10.88 v1(41.95,10.88)
UNNAMED_2_DIOLED_I84_P: length 4.1
  TOP w0.203: XD1.A 47.22,28.8 XR4.2
UNNAMED_2_ICPIC18F4550_I2_RC2CC: length 5.8
  TOP w0.203: XR4.1 46.23,23.49 45.59,22.86 43.81,22.86 43.25,22.3 XU2.36
UNNAMED_4_ADP3338_I421_IN: length 29.8
  TOP w0.508: C33.1 v1(56.01,169.04) ; U7.3 v1(18.57,169.9) ; C105.1 v1(36.2,168.78) ; v1(101.47,136.91) C1.P v1(101.47,133.86) ; U11.3 v1(37.97,169.77) ; U6.3 v1(57.3,169.65) ; U10.3 v1(78.64,169.65) ; C34.1 v1(17.02,168.91) ; C37.1 v1(77.34,168.66)
  L6_PWR w0.254: 99.96,154.18 P5.1 ; P5.1 101.6,155.82 ; P5.1 101.6,152.54 ; P5.1 103.24,154.18 ; P5.2 86.3,155.82 ; P5.2 87.94,154.18 ; P5.2 86.3,152.54 ; P5.2 84.66,154.18 ; 98.04,121.49 JP23.1 ; JP23.1 99.24,122.68 ; JP23.1 98.04,123.88 ; JP23.1 96.85,122.68
UNNAMED_4_CAP_I406_N1: length 8.4
  TOP w0.254: TP18.1 96.77,130.99 ; TP18.1 96.77,128.6 ; TP18.1 95.58,129.79 ; TP18.1 97.97,129.79 ; 96.85,125.22 JP23.2 ; JP23.2 99.24,125.22 ; JP23.2 98.04,126.42
UNNAMED_8_CAP_I44_N2: length 4.9
  TOP w0.203: X2.2 52.65,60.75 v1(53.09,61.19)
  BOTTOM w0.203: C104.2 53.09,63.26 R43.2 v1(53.09,61.19)
UNNAMED_8_CAP_I45_N2: length 4.9
  TOP w0.203: X2.3 52.14,60.86 v1(51.82,61.19)
  BOTTOM w0.203: C108.2 51.82,63.13 R43.1 v1(51.82,61.19)
UNNAMED_8_CAP_I48_N2: length 5.6
  TOP w0.203: v1(56.01,53.98) 55.74,53.71 X2.62
  BOTTOM w0.203: C109.2 v1(56.01,53.98) 55.02,53.98 R41.1
UNNAMED_8_CAP_I58_N1: length 25.2
  TOP w0.203: v2(54.61,58.04) 54.48,58.04 54.16,57.71 X2.70
  L3_SIGNAL w0.203: TP20.1 59.18,48.01 59.18,57.66 58.42,58.42 56.77,58.42 56.39,58.04 v2(54.61,58.04)
  BOTTOM w0.203: TP20.1 57.78,46.99 57.32,46.52 C118.1 57.32,41.92 57.02,41.63
UNNAMED_8_CAP_I67_N2: length 5.7
  TOP w0.203: v1(56.01,52.83) 55.88,52.83 55.5,53.21 X2.61
  BOTTOM w0.203: R41.2 55.14,52.83 v1(56.01,52.83) C119.2
UNNAMED_8_CNBNC5P_I79_CNTR: length 7.2
  BOTTOM w0.203: T3.3 J4.1
UNNAMED_8_DIOLED_I62_P: length 1.8
  TOP w0.203: DS4.A R29.2
UNNAMED_8_DIOLED_I63_P: length 1.9
  TOP w0.203: DS3.A R25.2
UNNAMED_8_NC3PJMPR_I72_A: length 16.1
  TOP w0.254: JP7.1 v2(66.04,84.2)
  BOTTOM w0.127: T1.1 69.22,73.91 68.2,72.9 67.42,72.9 67.06,73.26 67.06,82.32 66.75,82.63 66.29,82.63 66.04,82.88 v2(66.04,84.2)
UNNAMED_8_NC3PJMPR_I72_COM: length 38.9
  TOP w0.127: X2.67 54.21,56.21 54.33,56.09 57.49,56.09 R5.1 59.44,56.01 60.96,56.01 61.47,56.52 61.47,81.79 62.36,82.68 63.5,82.68 63.88,83.06 63.88,83.44 64.14,83.69 JP7.2
UNNAMED_8_NC3PJMPR_I73_A: length 16
  TOP w0.254: JP6.1 v2(66.04,80.9)
  BOTTOM w0.127: v2(66.04,80.9) 66.04,82.07 66.34,82.37 66.65,82.37 66.8,82.22 66.8,73.15 67.31,72.64 68.2,72.64 69.47,71.37 T1.3
UNNAMED_8_NC3PJMPR_I73_COM: length 38.9
  TOP w0.127: X2.66 54.21,55.71 54.33,55.83 57.45,55.83 58.42,54.86 ; 58.42,54.86 59.31,55.75 61.09,55.75 61.72,56.39 61.72,81.66 62.48,82.42 63.5,82.42 63.88,82.04 63.88,81.66 64.14,81.41 JP6.2 ; 58.42,54.86 R18.1
UNNAMED_8_RES_I59_N1: length 7.7
  TOP w0.203: X2.69 54.34,57.21 54.45,57.32 55.63,57.32 55.71,57.4 55.75,57.4 56.59,58.24 58.12,58.24 58.55,58.67 v1(58.55,59.56)
  BOTTOM w0.203: v1(58.55,59.56) R3.1
UNNAMED_8_RES_I82_N1: length 4.8
  TOP w0.203: R20.1 50.42,63.67 50.42,60.04 50.65,59.82 X2.6
UNNAMED_8_SKTQFN72PAD_I56_N5: length 34.7
  TOP w0.203: S3.1 S3.2 v1(66.17,54.1) ; X2.5 51.14,59.98 50.8,60.33 50.8,62.23 51.31,62.74 57.28,62.74 58.04,61.98 v1(60.33,61.98)
  BOTTOM w0.203: v1(60.33,61.98) 60.96,61.98 63.12,59.82 63.12,54.99 64.01,54.1 v1(66.17,54.1)
UNNAMED_8_XFMRETC1_I74_N3: length 3.5
  BOTTOM w0.203: 76.58,70.1 74.87,70.1 T1.4
UNNAMED_8_XFMRETC1_I74_N4: length 3.5
  BOTTOM w0.203: 76.58,75.18 74.87,75.18 T1.5
UNNAMED_11_AD9516_I1_BYPASS: length 15
  BOTTOM w0.203: U1.10 49.65,92.08 49.28,92.44 49.28,93.09 48.77,93.6 C4.2 47.59,96.04 C26.1 48.07,96.08 49.02,97.03 49.02,99.44 48.39,100.08 C3.2 C2.2
UNNAMED_11_AD9516_I1_CLK_1: length 2.4
  BOTTOM w0.203: U1.13 51.14,92.28 C18.2
UNNAMED_11_AD9516_I1_CLKN: length 2.3
  BOTTOM w0.203: C19.2 52.45,93.13 51.65,92.33 U1.14
UNNAMED_11_AD9516_I1_CP: length 7.6
  BOTTOM w0.203: U1.5 47.14,92.43 45.97,93.6 C4.1 45.21,94.27 R2.1 R1.2
UNNAMED_11_AD9516_I1_CPRSET: length 4.8
  BOTTOM w0.203: R12.2 41.66,90.42 42.59,89.49 U1.62
UNNAMED_11_AD9516_I1_LD: length 23.5
  TOP w0.203: v1(43.18,92.46) 43.18,97.92 42.42,98.68 42.42,100.2 v1(42.55,100.33) ; U15.3 40.52,101.21 39.37,102.36 TP14.1
  BOTTOM w0.203: v1(43.18,92.46) 43.56,92.08 45.72,92.08 46.14,91.65 U1.3 ; v1(42.55,100.33) 41.4,100.33 39.37,102.36 TP14.1
UNNAMED_11_AD9516_I1_LF: length 16.1
  TOP w0.203: v1(43.56,99.06) 48.64,93.98 v1(48.64,92.71)
  BOTTOM w0.203: C2.1 44.56,102.11 43.56,101.33 v1(43.56,99.06) 43.05,98.55 R1.1 ; U1.9 49.14,91.7 48.64,92.2 v1(48.64,92.71)
UNNAMED_11_AD9516_I1_REFIN1: length 16.7
  BOTTOM w0.203: U1.64 42.35,90.49 41.53,91.31 37.34,91.31 36.7,90.68 36.7,83.4 C29.2
UNNAMED_11_AD9516_I1_REFMON: length 16.3
  TOP w0.203: TP15.1 41.52,102.48 U15.1 41.53,99.38 41.53,98.17 42.29,97.4 v1(42.29,92.96) ; v1(42.29,91.69) 42.29,91.06 42.93,90.42 45.17,90.42 45.34,90.26 v1(45.38,90.26)
  BOTTOM w0.203: U1.2 45.65,90.6 45.38,90.34 v1(45.38,90.26) ; v1(42.29,92.96) v1(42.29,91.69)
UNNAMED_11_AD9516_I1_RESETN: length 41.7
  TOP w0.203: v1(64.9,65.15) 64.9,64.01 S1.4 S1.3 ; v1(55.5,67.06) 55.5,86.61 54.62,87.49 v2(54.6,87.49)
  BOTTOM w0.203: v1(64.9,65.15) 64.9,65.41 63.25,67.06 v1(55.5,67.06) ; U1.23 v2(54.6,87.49)
UNNAMED_11_AD9516_I1_RSET: length 4.9
  BOTTOM w0.203: R11.2 41.27,89.03 42.55,87.76 43.43,87.76 43.7,87.49 U1.58
UNNAMED_11_AD9516_I1_STATUS: length 13.5
  TOP w0.203: TP13.1 40.52,93.1 U15.6
  L3_SIGNAL w0.203: TP13.1 41.15,93.73 43.05,93.73 43.69,93.09 47.24,93.09 47.75,92.58 v2(47.75,92.33)
  BOTTOM w0.203: U1.6 47.65,92.22 v2(47.75,92.33)
UNNAMED_11_CAP_I46_N1: length 7.5
  BOTTOM w0.203: C29.1 37.47,79.12 R9.1 J2.1
UNNAMED_11_CAP_I224_N1: length 13.1
  BOTTOM w0.457: C18.1 50.16,96.39 R6.1 50.67,98.8 CR4.3 50.04,102.74 51.18,103.89 T2.1
UNNAMED_11_CAP_I226_N1: length 8.5
  BOTTOM w0.457: C19.1 52.45,96.39 R6.2 51.94,98.41 CR4.2 CR4.1 52.33,100.71 52.96,101.35 T2.3
UNNAMED_11_CAP_I235_N1: length 2.6
  BOTTOM w0.203: C3.1 45.25,97.54 R2.2
UNNAMED_11_CNBNC5P_I230_CNTR: length 15.2
  BOTTOM w0.203: T2.5 59.94,103.89 66.67,110.62 J1.1
UNNAMED_11_DIOLED_I108_P: length 2
  TOP w0.203: R14.2 CR3.A
UNNAMED_11_DIOLED_I260_P: length 2
  TOP w0.203: R13.2 DS2.A
UNNAMED_11_DIOLED_I261_P: length 2.2
  TOP w0.203: R10.2 DS1.A
UNNAMED_11_RES_I113_N1: length 4.2
  TOP w0.203: U15.7 41.02,97.54 40.76,97.79 38.82,97.79 R14.1
UNNAMED_11_RES_I114_N1: length 3.3
  TOP w0.203: U15.5 40.02,95.64 39.24,94.87 R13.1
UNNAMED_11_RES_I115_N1: length 3.8
  TOP w0.203: U15.2 41.02,98.93 40.64,98.55 38.7,98.55 R10.1
UNNAMED_12_CAP_I386_N1: length 98.6
  TOP w0.203: v2(54.48,119.51) 54.28,119.31 X1.70
  L3_SIGNAL w0.203: v1(57.32,108.93) 59.98,108.93 64.52,104.39 64.52,77.34 64.01,76.84 64.01,39.24 v1(64.52,38.73)
  L8_SIGNAL w0.203: v1(57.32,108.93) 57.02,109.22 57.02,111.89 55.12,113.79 55.12,115.82 55.5,116.2 55.5,119 54.99,119.51 v2(54.48,119.51)
  BOTTOM w0.203: v1(64.52,38.73) TP16.1 57.02,38.73 ; C91.1 v1(57.32,108.93)
UNNAMED_12_CAP_I532_N2: length 4.4
  TOP w0.203: v1(52.96,122.53) 52.65,122.22 X1.2
  BOTTOM w0.203: v1(52.96,122.53) R22.2 52.96,124.6 C103.2
UNNAMED_12_CAP_I533_N2: length 4.5
  TOP w0.203: v1(51.69,122.68) 51.69,122.53 52.14,122.07 X1.3
  BOTTOM w0.203: v1(51.69,122.68) 51.69,124.47 C107.2
UNNAMED_12_CAP_I534_N2: length 5.3
  TOP w0.203: v1(56.01,115.54) 55.77,115.31 X1.62
  BOTTOM w0.127: C93.2 57.78,115.54 v1(56.01,115.54)
  BOTTOM w0.203: v1(56.01,115.54) R38.1
UNNAMED_12_CAP_I535_N2: length 5.5
  TOP w0.203: X1.61 55.48,114.81 55.75,114.53 v1(56.01,114.53)
  BOTTOM w0.127: v1(56.01,114.53) 57.78,114.53 C133.2
  BOTTOM w0.203: v1(56.01,114.53) 55.75,114.27 R38.2
UNNAMED_12_CNBNC5P_I550_CNTR: length 6.5
  BOTTOM w0.203: J3.1 T7.1
UNNAMED_12_DIOLED_I528_P: length 1.8
  TOP w0.203: R16.2 CR5.A
UNNAMED_12_DIOLED_I529_P: length 1.8
  TOP w0.203: R39.2 CR6.A
UNNAMED_12_NC3PJMPR_I562_A: length 16.3
  TOP w0.254: 65.02,89.28 v1(66.04,89.28)
  BOTTOM w0.127: T5.3 69.47,99.44 68.33,100.58 67.56,100.58 66.93,99.95 66.93,91.06 66.67,90.81 66.17,90.81 66.04,90.68 v1(66.04,89.28)
UNNAMED_12_NC3PJMPR_I562_COM: length 38.9
  TOP w0.127: JP5.2 64.14,89.79 63.88,90.04 63.88,90.42 63.5,90.81 61.98,90.81 61.59,91.19 61.59,116.97 61.18,117.39 59.35,117.39 58.42,116.46 ; 58.42,116.46 R19.1 ; 58.42,116.46 57.45,117.43 54.33,117.43 54.21,117.31 X1.66
UNNAMED_12_NC3PJMPR_I563_A: length 16.3
  TOP w0.254: JP4.1 v1(66.04,92.58)
  BOTTOM w0.127: T5.1 69.47,101.98 68.33,100.84 67.46,100.84 66.67,100.05 66.67,91.16 66.57,91.06 66.17,91.06 66.04,91.19 v1(66.04,92.58)
UNNAMED_12_NC3PJMPR_I563_COM: length 38.9
  TOP w0.127: JP4.2 64.14,92.08 63.88,91.82 63.88,91.44 63.5,91.06 62.23,91.06 61.85,91.44 61.85,117.22 61.43,117.64 59.37,117.64 R4.1 57.51,117.68 54.33,117.68 54.21,117.81 X1.67
UNNAMED_12_RES_I387_N1: length 7.4
  TOP w0.203: v1(58.55,120.88) 57.51,119.84 56.59,119.84 55.75,119 55.71,119 55.63,118.92 54.45,118.92 54.34,118.81 X1.69
  BOTTOM w0.203: R21.1 v1(58.55,120.88)
UNNAMED_12_RES_I574_N1: length 4.9
  TOP w0.203: X1.6 50.65,121.31 50.16,121.79 50.16,124.85 R40.1
UNNAMED_12_SKTQFN72PAD_I319_N5: length 29
  TOP w0.203: X1.5 51.14,121.35 50.91,121.58 50.91,123.81 51.44,124.33 55.63,124.33 57.91,126.62 65,126.62 S2.1 S2.2
UNNAMED_12_XFMRETC1_I551_N3: length 3.6
  BOTTOM w0.203: T5.4 73.91,99.44 75.18,98.17 T7.4
UNNAMED_12_XFMRETC1_I551_N4: length 3.6
  BOTTOM w0.203: T7.6 75.18,103.25 73.91,101.98 T5.5
UNNAMED_13_ICSY89833_I43_Q0: length 2.5
  BOTTOM w0.203: R31.1 15.63,83.31 15.24,83.69 U3.15
UNNAMED_13_ICSY89833_I43_Q0N: length 2.3
  BOTTOM w0.203: R31.2 14.48,83.43 14.74,83.69 U3.16
UNNAMED_13_ICSY89833_I43_Q3: length 2.5
  BOTTOM w0.203: U3.5 14.74,88.9 14.35,89.29 R30.2
UNNAMED_13_ICSY89833_I43_Q3N: length 2.5
  BOTTOM w0.203: R30.1 15.62,89.81 15.44,89.63 15.44,89.53 15.34,89.43 15.34,89.12 15.24,89.03 U3.6
USB_D+: length 27.1
  TOP w0.127: XU2.43 38.7,21.81 38.95,22.06 38.95,22.42 38.38,22.99 28.57,22.99 26.16,20.57 26.16,9.78 26.42,9.52 XP2.3
USB_D-: length 28
  TOP w0.127: XP2.2 25.62,9.49 25.91,9.78 25.91,20.75 28.42,23.27 38.48,23.27 39.12,22.63 39.12,22.61 39.2,22.52 39.2,21.99 39.35,21.84 XU2.42
USB_VCC: length 20.7
  TOP w0.279: XU2.28 45.85,17.53 v1(46.1,17.78) 45.71,18.18 XU2.29
  TOP w0.305: XU1.14 v3(59.1,27.35)
  TOP w0.381: XP2.1 v1(24.82,9.91) ; v1(34.92,28.58) 34.46,28.11 XU3.14 ; XU2.8 36.63,16.23 v1(36.32,16.54) 36.66,16.88 XU2.7
  TOP w0.508: v3(49.91,19.3) 49.53,18.92 XC8.1 ; XC6.1 v1(34.43,19.55) ; XC7.1 v1(34.46,17.06) ; XC4.P v1(51.05,18.11) ; XR2.1 v1(41.02,4.45) ; XC5.1 v3(47.42,19)
  L5_PWR w0.254: 45.49,6.39 XP1.2 ; XP1.2 44.23,7.65 ; XP1.2 45.49,8.9 ; XP1.2 46.75,7.65
XCVDD33: length 59.2
  TOP w0.203: U15.8 41.52,96.13 v3(41.15,95.76)
  TOP w0.305: v3(44.07,82.17) 44.07,83.19 44.45,83.57 C17.1
  TOP w0.381: TP11.1 32.64,158.29 ; TP11.1 33.83,157.1 ; TP11.1 32.64,155.9 ; TP11.1 31.44,157.1 ; XU3.1 v1(34.46,34.63)
  TOP w0.508: C16.1 v1(49.91,81.15) ; C21.1 v3(42.93,82.04) ; 50.29,90.81 v3(50.29,92.08) C12.1 ; XR5.1 v1(28.32,29.97) ; v1(34.16,160.66) 34.16,160.72 E6.2 32.51,161.1 v1(32.51,160.66) ; 44.96,93.09 45.34,93.47 C9.1 46.48,92.46 v2(46.36,92.33) ; C14.1 54.1,83.82 v3(54.36,83.57) ; C7.1 v1(43.43,88.65) 43.81,89.03 C20.1 ; v2(54.48,85.49) 54.46,85.47 C11.1 ; C15.1 v3(54.1,82.68)
  L5_PWR w0.254: TP11.1 33.83,157.1 ; TP11.1 32.64,155.9 ; TP11.1 32.64,158.29 ; TP11.1 31.44,157.1
  BOTTOM w0.203: U1.38 50.14,81.39 v1(49.91,81.15) ; U1.31 54.28,83.49 v3(54.36,83.57) 53.93,83.99 U1.30 ; v3(54.1,82.68) 53.79,82.99 U1.32
  BOTTOM w0.229: U3.7 15.74,88.77
  BOTTOM w0.254: v2(46.36,92.33) 46.48,92.2 46.48,91.95 46.65,91.78 U1.4 ; U1.12 50.65,91.72 v3(50.29,92.08) 50.14,91.93 U1.11 ; U1.60 43.59,88.49 v1(43.43,88.65) 43.78,88.99 U1.61 ; U1.1 43.51,91.24 v1(43.43,91.31) ; U1.41 v1(48.65,81.15)
  BOTTOM w0.279: v1(16,84.45) 16,84.58 15.74,84.84 U3.14 ; 15.74,88.77 16.36,89.39 16.78,89.39 C66.1 C25.1
  BOTTOM w0.305: U1.54 v3(43.2,85.49) ; U1.49 44.39,82.49 v3(44.07,82.17) ; U1.57 v2(43.57,86.99) ; U1.50 v3(43.38,83.49) 43.88,83.99 U1.51 ; U1.27 v2(54.48,85.49)
  BOTTOM w0.508: C25.1 17.56,93.05 v1(17.27,93.34) ; C70.1 C67.1 18.71,84.8 v1(18.29,85.22)
  vias: v1(31.12,160.66) v1(31.12,159.26) v1(32.51,159.26) v1(34.29,159.26) v1(35.56,160.66) v1(35.56,159.26)

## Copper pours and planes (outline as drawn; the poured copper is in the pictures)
AVDD5 on TOP (solid shape): 85.85,129.54 85.85,128.14 84.96,127.25 84.96,122.3 84.2,121.54 81.66,121.54 81.15,122.05 81.15,129.54 81.41,129.79 85.6,129.79
AVDD5 on L5_PWR: 85.72,77.09 82.42,73.79 82.42,56.64 84.58,54.48 104.39,54.48 104.39,79.76 98.04,79.76 97.79,80.01 97.79,93.85 104.14,93.85 104.39,94.11 104.39,113.66 94.11,113.66 93.98,113.54 86.74,113.54 86.87,113.66 86.87,127.13 88.39,128.65 88.39,130.18 80.77,130.18 80.64,130.05 80.64,120.52 80.71,120.46 80.71,102.81 85.72,97.79
AVDD33 on TOP: 76.96,161.93 76.96,155.07 76.71,154.81 70.61,154.81 70.23,155.19 70.23,161.8 70.61,162.18 76.71,162.18
AVDD33 on L5_PWR: 68.71,132.97 55.63,132.97 52.32,129.67 52.32,113.28 52.58,113.03 52.58,111.89 53.34,111.12 63.37,111.12 63.37,72.26 63.5,72.14 51.69,72.14 51.44,71.88 51.44,57.4 52.2,57.4 52.2,49.4 53.61,49.4 53.61,42.04 53.59,42.02 53.59,39.75 76.58,39.75 81.28,44.45 81.28,75.56 84.45,78.74 84.45,90.55 79.5,95.5 79.5,131.95 81.79,131.95 81.79,161.93 81.66,162.05 68.71,162.05
DVDD18 on TOP: 16.64,162.05 16.64,155.32 16.38,155.07 10.29,155.07 9.91,155.45 9.91,161.93 10.41,162.43 16.26,162.43
DVDD18 on L6_PWR: 50.8,34.16 50.67,34.29 38.23,34.29 34.8,37.72 14.48,37.72 14.48,19.94 46.23,19.94 48.13,18.03 48.13,16.26 48.01,16.13 34.42,16.13 33.53,17.02 14.61,17.02 14.48,16.89 14.48,7.11 14.35,6.98 1.78,6.98 1.78,162.81 27.56,162.81 27.56,143.51 27.59,140.84 46.61,140.84 46.61,128.52 50.8,128.52 50.93,128.4 50.93,125.86 50.8,119 50.8,114.68 50.93,105.41 50.93,101.35 50.04,100.46 27.43,100.46 27.43,73.41 51.18,73.41 51.18,57.53 50.16,57.53 50.04,57.4 50.04,51.56 51.44,51.56 51.44,49.66 56.13,49.66 56.13,42.93 57.66,42.93 61.59,38.99 61.59,29.46 61.34,29.21 50.8,29.21
APLANE on TOP, BOTTOM: 0.63,178.44 0.63,0.63 106.55,0.63 106.55,178.44
APLANE on L2_GND: 0.38,0.63 0.51,178.44 106.62,178.44 106.68,178.38 106.43,0.51
APLANE on L4_GND: 0.63,178.31 0.89,0.51 106.55,0.63 106.3,178.44
APLANE on L7_GND: 0.63,178.56 0.63,0.63 105.92,0.63 106.05,178.31
APLANE on L9_GND: 0.38,178.44 0.38,0.63 106.17,0.63 106.17,178.31
CVDD18 on TOP: 55.63,161.93 55.63,155.07 55.37,154.81 49.28,154.81 48.9,155.19 48.9,161.8 49.28,162.18 55.37,162.18
CVDD18 on L6_PWR: 79.12,51.31 52.32,51.31 51.44,52.2 51.44,71.25 52.45,72.26 52.32,119.25 51.31,119.25 51.31,129.16 48.64,129.16 48.51,129.29 48.51,162.31 64.26,162.31 64.26,145.29 64.14,145.16 64.14,130.81 71.75,130.81 71.75,101.6 79.12,94.23
UNNAMED_4_ADP3338_I421_IN on L6_PWR: 106.55,82.55 102.74,82.55 102.62,82.68 98.55,82.68 98.42,82.8 85.09,82.8 83.95,83.95 83.95,104.78 79.5,104.78 79.5,164.21 1.78,164.21 1.78,178.56 2.67,178.56 100.33,178.44 106.55,178.44
UNNAMED_4_ADP3338_I421_OUT1 on TOP (solid shape): 61.85,174.37 61.85,168.78 59.94,168.78 59.94,172.85 59.56,173.23 54.61,173.23 54.61,176.4 59.05,176.4
UNNAMED_4_ADP3338_I428_OUT1 on TOP (solid shape): 83.31,174.24 83.31,168.66 81.28,168.66 81.15,168.78 81.15,173.1 75.95,173.1 75.95,176.28 81.28,176.28
UNNAMED_4_ADP3338_I429_OUT1 on TOP (solid shape): 42.29,174.37 42.29,168.78 40.26,168.78 40.13,168.91 40.13,173.23 34.92,173.23 34.92,176.4 40.26,176.4
UNNAMED_4_ADP3338_I441_OUT1 on TOP (solid shape): 22.99,174.5 22.99,168.91 20.96,168.91 20.83,169.04 20.83,173.36 15.62,173.36 15.62,176.53 20.96,176.53
UNNAMED_4_CAP_I24_N1 on TOP (solid shape): 54.1,167.13 54.48,167.13 54.48,165.23 51.56,165.23 51.56,171.58 51.31,171.83 51.31,175.39 51.24,175.45 51.24,176.09 52.01,176.85 54.1,176.85
UNNAMED_4_CAP_I39_N1 on TOP (solid shape): 15.11,167.39 15.49,167.39 15.49,165.48 12.57,165.48 12.57,171.83 12.32,172.08 11.94,172.08 11.94,176.02 12.95,177.04 15.11,177.04
UNNAMED_4_CAP_I133_N1 on TOP (solid shape): 75.44,167.13 75.82,167.13 75.82,165.23 73.15,165.23 73.28,165.35 73.28,172.08 72.26,172.08 72.26,175.77 73.41,176.91 75.44,176.91
UNNAMED_4_CAP_I150_N1 on TOP (solid shape): 34.16,167.51 34.54,167.51 34.54,165.35 31.62,165.35 31.62,171.83 31.24,172.21 31.24,175.89 31.31,175.96 31.31,176.47 32.13,177.29 34.16,177.29
UNNAMED_4_CAP_I406_N1 on TOP: 94.62,127.51 94.62,131.95 98.55,131.95 98.55,127.89 99.44,127 99.44,124.08 97.03,124.08 95.25,122.3 88.9,122.3 87.88,123.32 87.88,126.87 88.14,127.13 89.66,127.13 90.04,126.75 93.85,126.75
USB_VCC on L5_PWR: 20.19,0.51 20.21,11.2 20.83,11.81 24.26,11.81 28.32,15.88 28.32,27.05 33.27,32 61.21,32 61.85,31.37 61.85,1.27 61.09,0.51
XCVDD33 on TOP: 36.32,161.93 36.32,159.13 35.31,158.12 35.31,154.43 35.18,154.31 28.07,154.31 27.94,154.43 27.94,161.8 28.45,162.31 35.94,162.31
XCVDD33 on L5_PWR: 42.42,143.64 42.29,143.51 42.29,131.7 39.5,131.7 35.31,127.51 35.31,105.41 35.56,105.16 57.4,105.16 57.4,77.98 42.29,77.98 42.16,78.11 35.56,78.11 35.62,78.04 35.62,34.86 28.83,28.07 7.87,28.07 1.78,34.16 1.78,131.95 27.18,131.95 27.05,132.08 27.05,162.56 42.42,162.56

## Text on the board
BOTTOM: 12050 REV B
Ref Des/Silkscreen Bottom: DESIGNED IN U.S.A.
Ref Des/Silkscreen Top: 1 | 3 | DVDD1.8 | XCVDD3.3 | AD9516_REFIN | CVDD1.8 | AD9142_RESET | AD9516_CLKIN | AVDD3.3 | GND | 5V | DAC2 OUTPUT | DAC1 OUTPUT | MOD_OUT | LO_IN | REV B | AD9139-DUAL-EBZ
L8_SIGNAL: L4 SIGNAL
PAGE_OUTLINE: B | SILK SCREEN UPDATE | 14NOV12 | 14FEB14 | M.V. | J.G. | SOCKETED BOARD
DIMENSION: 15.    0.015 VIAS TO BE NON-CONDUCTIVE EPOXY FILLED, AND GROUND | FLUSH PRIOR TO OVER PLATING. | DIFFERENTIAL IMPEDANCE = 100 OHMS +/- 10% | ARTWORK LINE WIDTH FOR | IMPEDANCE CONTROLLED LINES = 0.005" | FOR LAYER 1 AND 10. | FOR LAYER 1,4,7 AND 10. | SEE NOTE 15
User.8: L2 GND
User.9: L3 SIGNAL
User.10: IMMERSION GOLD OVER 100-200 MICROINCHES OF ELECTROLESS NICKEL. | 14.    FINISH: SURFACES SHALL HAVE ENIG FINISH PLATED WITH 2-6 MICROINCHES OF
User.11: L4 GND
User.12: L5 PWR
User.13: L6 PWR
User.14: L7 GND
User.15: L8 SIGNAL
User.16: L9 GND
User.17: 0.0051" | 0.0060" | 0.0074" | 0.0035" | 0.0037"
User.19: L10 SIGNAL
User.20: L11 GND
User.22: SECONDARY SIDE
User.31: FIGURE | SIZE | 10.0 | 15.0 | 16.0 | 25.0 | 40.0 | 45.0 | 60.0 | 63.0 | 75.0 | 33.0 | 155.0 | PLATED | NON-PLATED | FINISHED HOLES IN MILS | ALL UNITS ARE IN MILS | QTY | 171 | 183 | 643 | 120 | 20 | 6 | 5 | 4 | 2 | 8 | TOLERANCE/NOTES
